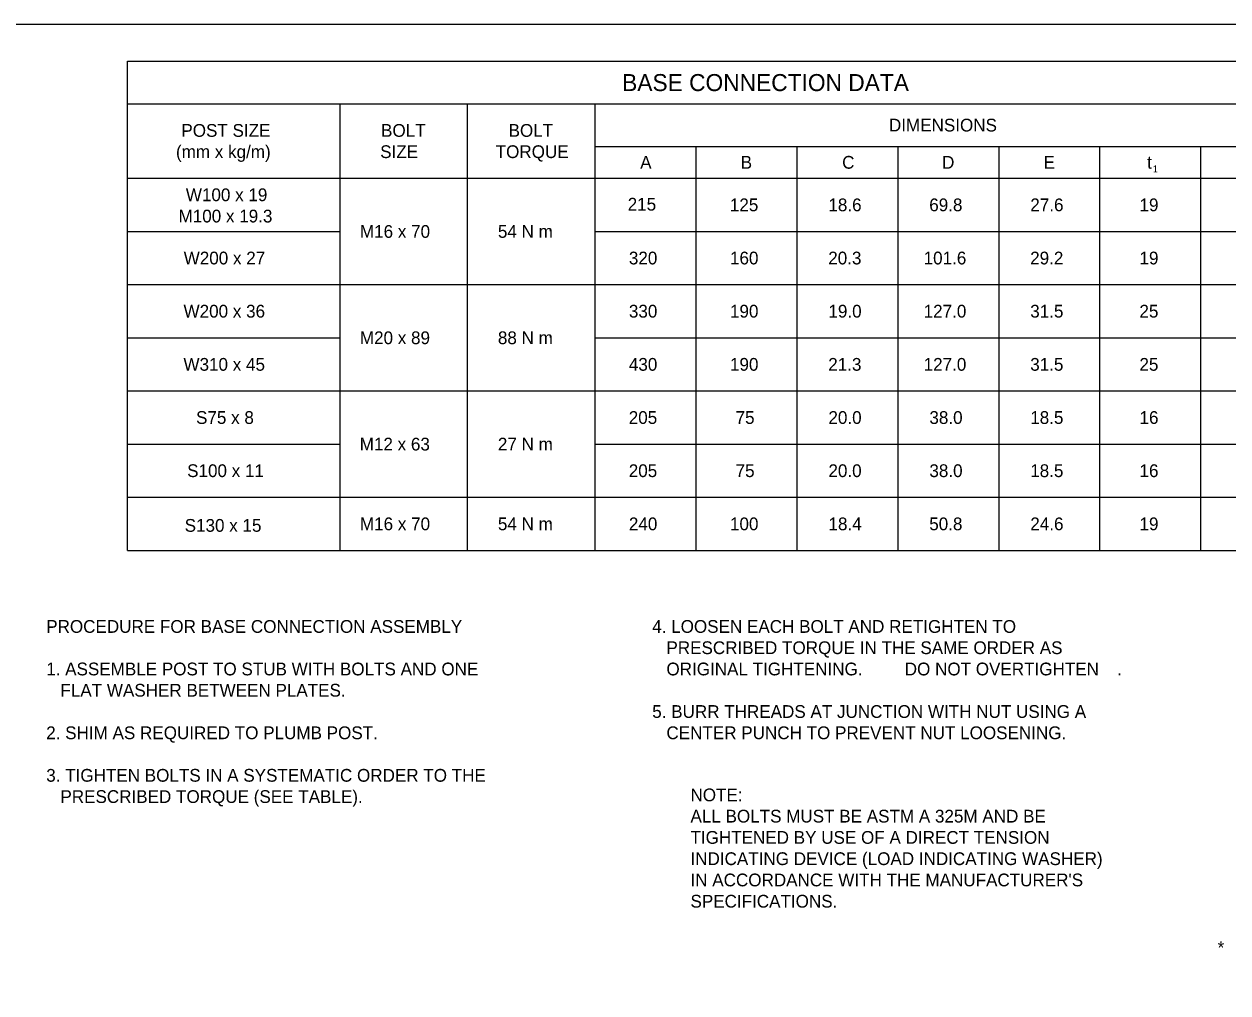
# Model space of a CAD drawing. Extents: x 49991.4 to 50021, y 49987.6 to 50011.4.
# Drawn here: x 50002.29 to 50007.95, y 49994.44 to 49999 of the extents above; entities that cross this region are included whole.
import ezdxf

# ---------------------------------------------------------------- set-up
doc = ezdxf.new("R2010")
doc.units = 0
doc.layers.add('Level 1', color=7, linetype='Continuous')
doc.layers.add('Level 2', color=7, linetype='Continuous')

msp = doc.modelspace()

# ---------------------------------------------------------------- linework, layer by layer
at = {"layer": 'Level 1'}
msp.add_lwpolyline([(49999.3835, 49998.9992), (50016.7501, 49998.9992), (50016.7501, 49987.7988), (49999.3835, 49987.7988)], close=True, dxfattribs=at)
at = {"layer": 'Level 2'}
for p, q in [((50002.7742, 49998.8242), (50016.4992, 49998.8242)), ((50002.7742, 49996.5242), (50002.7742, 49998.8242)), ((50002.7742, 49998.6242), (50016.4992, 49998.6242)), ((50003.7742, 49996.5242), (50003.7742, 49998.6242)), ((50004.3742, 49996.5242), (50004.3742, 49998.6242)), ((50004.9742, 49996.5242), (50004.9742, 49998.6242)), ((50004.9742, 49998.4242), (50008.2992, 49998.4242)), ((50005.4492, 49996.5242), (50005.4492, 49998.4242)), ((50005.9242, 49996.5242), (50005.9242, 49998.4242)), ((50006.3992, 49996.5242), (50006.3992, 49998.4242)), ((50006.8742, 49996.5242), (50006.8742, 49998.4242)), ((50007.3492, 49996.5242), (50007.3492, 49998.4242)), ((50007.8242, 49996.5242), (50007.8242, 49998.4242)), ((50002.7742, 49998.2742), (50016.4992, 49998.2742)), ((50002.7742, 49998.0242), (50003.7742, 49998.0242)), ((50004.9742, 49998.0242), (50016.4992, 49998.0242)), ((50002.7742, 49997.7742), (50016.4992, 49997.7742)), ((50002.7742, 49997.5242), (50003.7742, 49997.5242)), ((50004.9742, 49997.5242), (50016.4992, 49997.5242)), ((50002.7742, 49997.2742), (50016.4992, 49997.2742)), ((50002.7742, 49997.0242), (50003.7742, 49997.0242)), ((50004.9742, 49997.0242), (50016.4992, 49997.0242)), ((50002.7742, 49996.7742), (50016.4992, 49996.7742)), ((50002.7742, 49996.5242), (50016.4992, 49996.5242))]:
    msp.add_line(p, q, dxfattribs=at)

# ---------------------------------------------------------------- texts
for s, height, p in [('BASE CONNECTION DATA', 0.08, (50005.1011, 49998.6842)), ('POST SIZE', 0.06, (50003.0273, 49998.4692)), ('BOLT', 0.06, (50003.9668, 49998.4692)), ('BOLT', 0.06, (50004.5668, 49998.4692)), ('DIMENSIONS', 0.06, (50006.3564, 49998.4942)), ('(mm x kg/m)', 0.06, (50003.0019, 49998.3692)), ('SIZE', 0.06, (50003.9627, 49998.3692)), ('TORQUE', 0.06, (50004.5061, 49998.3692)), ('A', 0.06, (50005.186, 49998.3192)), ('B', 0.06, (50005.659, 49998.3192)), ('C', 0.06, (50006.1362, 49998.3192)), ('D', 0.06, (50006.6064, 49998.3192)), ('E', 0.06, (50007.0837, 49998.3192)), ('t', 0.06, (50007.5711, 49998.3192)), ('1', 0.0325, (50007.5978, 49998.3019)), ('W100 x 19', 0.06, (50003.0483, 49998.1665)), ('215', 0.06, (50005.1272, 49998.1222)), ('125', 0.06, (50005.6079, 49998.1192)), ('18.6', 0.06, (50006.0715, 49998.1192)), ('69.8', 0.06, (50006.546, 49998.1192)), ('27.6', 0.06, (50007.0215, 49998.1192)), ('19', 0.06, (50007.5353, 49998.1192)), ('  M100 x 19.3', 0.06, (50002.9695, 49998.0665)), ('M16 x 70', 0.06, (50003.8674, 49997.9942)), ('54 N m', 0.06, (50004.5165, 49997.9942)), ('.', 0.06, (50004.7527, 49998.0242)), ('W200 x 27', 0.06, (50003.0382, 49997.8692)), ('320', 0.06, (50005.1328, 49997.8692)), ('160', 0.06, (50005.6085, 49997.8692)), ('20.3', 0.06, (50006.0708, 49997.8692)), ('101.6', 0.06, (50006.5196, 49997.8692)), ('29.2', 0.06, (50007.0209, 49997.8692)), ('19', 0.06, (50007.5353, 49997.8692)), ('W200 x 36', 0.06, (50003.0375, 49997.6192)), ('330', 0.06, (50005.1328, 49997.6192)), ('190', 0.06, (50005.6085, 49997.6192)), ('19.0', 0.06, (50006.0717, 49997.6192)), ('127.0', 0.06, (50006.5197, 49997.6192)), ('31.5', 0.06, (50007.0211, 49997.6192)), ('25', 0.06, (50007.5349, 49997.6192)), ('M20 x 89', 0.06, (50003.8671, 49997.4942)), ('88 N m', 0.06, (50004.5165, 49997.4942)), ('.', 0.06, (50004.7527, 49997.5242)), ('W310 x 45', 0.06, (50003.0371, 49997.3692)), ('430', 0.06, (50005.1328, 49997.3692)), ('190', 0.06, (50005.6085, 49997.3692)), ('21.3', 0.06, (50006.0708, 49997.3692)), ('127.0', 0.06, (50006.5197, 49997.3692)), ('31.5', 0.06, (50007.0211, 49997.3692)), ('25', 0.06, (50007.5349, 49997.3692)), ('S75 x 8', 0.06, (50003.0963, 49997.1192)), ('205', 0.06, (50005.1322, 49997.1192)), ('75', 0.06, (50005.6349, 49997.1192)), ('20.0', 0.06, (50006.0717, 49997.1192)), ('38.0', 0.06, (50006.5467, 49997.1192)), ('18.5', 0.06, (50007.0211, 49997.1192)), ('16', 0.06, (50007.5353, 49997.1192)), ('M12 x 63', 0.06, (50003.8664, 49996.9942)), ('27 N m', 0.06, (50004.5165, 49996.9942)), ('.', 0.06, (50004.7527, 49997.0242)), ('S100 x 11', 0.06, (50003.0545, 49996.8692)), ('205', 0.06, (50005.1322, 49996.8692)), ('75', 0.06, (50005.6349, 49996.8692)), ('20.0', 0.06, (50006.0717, 49996.8692)), ('38.0', 0.06, (50006.5467, 49996.8692)), ('18.5', 0.06, (50007.0211, 49996.8692)), ('16', 0.06, (50007.5353, 49996.8692)), ('S130 x 15', 0.06, (50003.0428, 49996.612)), ('M16 x 70', 0.06, (50003.8674, 49996.6192)), ('54 N m', 0.06, (50004.5165, 49996.6192)), ('.', 0.06, (50004.7527, 49996.6492)), ('240', 0.06, (50005.1328, 49996.6192)), ('100', 0.06, (50005.6085, 49996.6192)), ('18.4', 0.06, (50006.072, 49996.6192)), ('50.8', 0.06, (50006.546, 49996.6192)), ('24.6', 0.06, (50007.0215, 49996.6192)), ('19', 0.06, (50007.5353, 49996.6192)), ('PROCEDURE FOR BASE CONNECTION ASSEMBLY', 0.06, (50002.3914, 49996.1368)), ('4. LOOSEN EACH BOLT AND RETIGHTEN TO', 0.06, (50005.2426, 49996.1368)), ('   PRESCRIBED TORQUE IN THE SAME ORDER AS', 0.06, (50005.2426, 49996.0368)), ('1. ASSEMBLE POST TO STUB WITH BOLTS AND ONE', 0.06, (50002.3914, 49995.9368)), ('   ORIGINAL TIGHTENING. ', 0.06, (50005.2426, 49995.9368)), ('DO NOT OVERTIGHTEN', 0.06, (50006.4307, 49995.9368)), ('.', 0.06, (50007.4301, 49995.9368)), ('   FLAT WASHER BETWEEN PLATES.', 0.06, (50002.3914, 49995.8368)), ('5. BURR THREADS AT JUNCTION WITH NUT USING A', 0.06, (50005.2426, 49995.7368)), ('2. SHIM AS REQUIRED TO PLUMB POST.', 0.06, (50002.3914, 49995.6368)), ('   CENTER PUNCH TO PREVENT NUT LOOSENING.', 0.06, (50005.2426, 49995.6368)), ('3. TIGHTEN BOLTS IN A SYSTEMATIC ORDER TO THE', 0.06, (50002.3914, 49995.4368)), ('   PRESCRIBED TORQUE (SEE TABLE).', 0.06, (50002.3914, 49995.3368)), ('NOTE:', 0.06, (50005.4226, 49995.3448)), ('ALL BOLTS MUST BE ASTM A 325M AND BE', 0.06, (50005.4226, 49995.2448)), ('TIGHTENED BY USE OF A DIRECT TENSION', 0.06, (50005.4226, 49995.1448)), ('INDICATING DEVICE (LOAD INDICATING WASHER)', 0.06, (50005.4226, 49995.0448)), ("IN ACCORDANCE WITH THE MANUFACTURER'S", 0.06, (50005.4226, 49994.9448)), ('SPECIFICATIONS.', 0.06, (50005.4226, 49994.8448)), ('*', 0.06, (50007.9029, 49994.6267))]:
    msp.add_text(s, height=height, dxfattribs=at).set_placement(p)

doc.saveas('drawing.dxf')
